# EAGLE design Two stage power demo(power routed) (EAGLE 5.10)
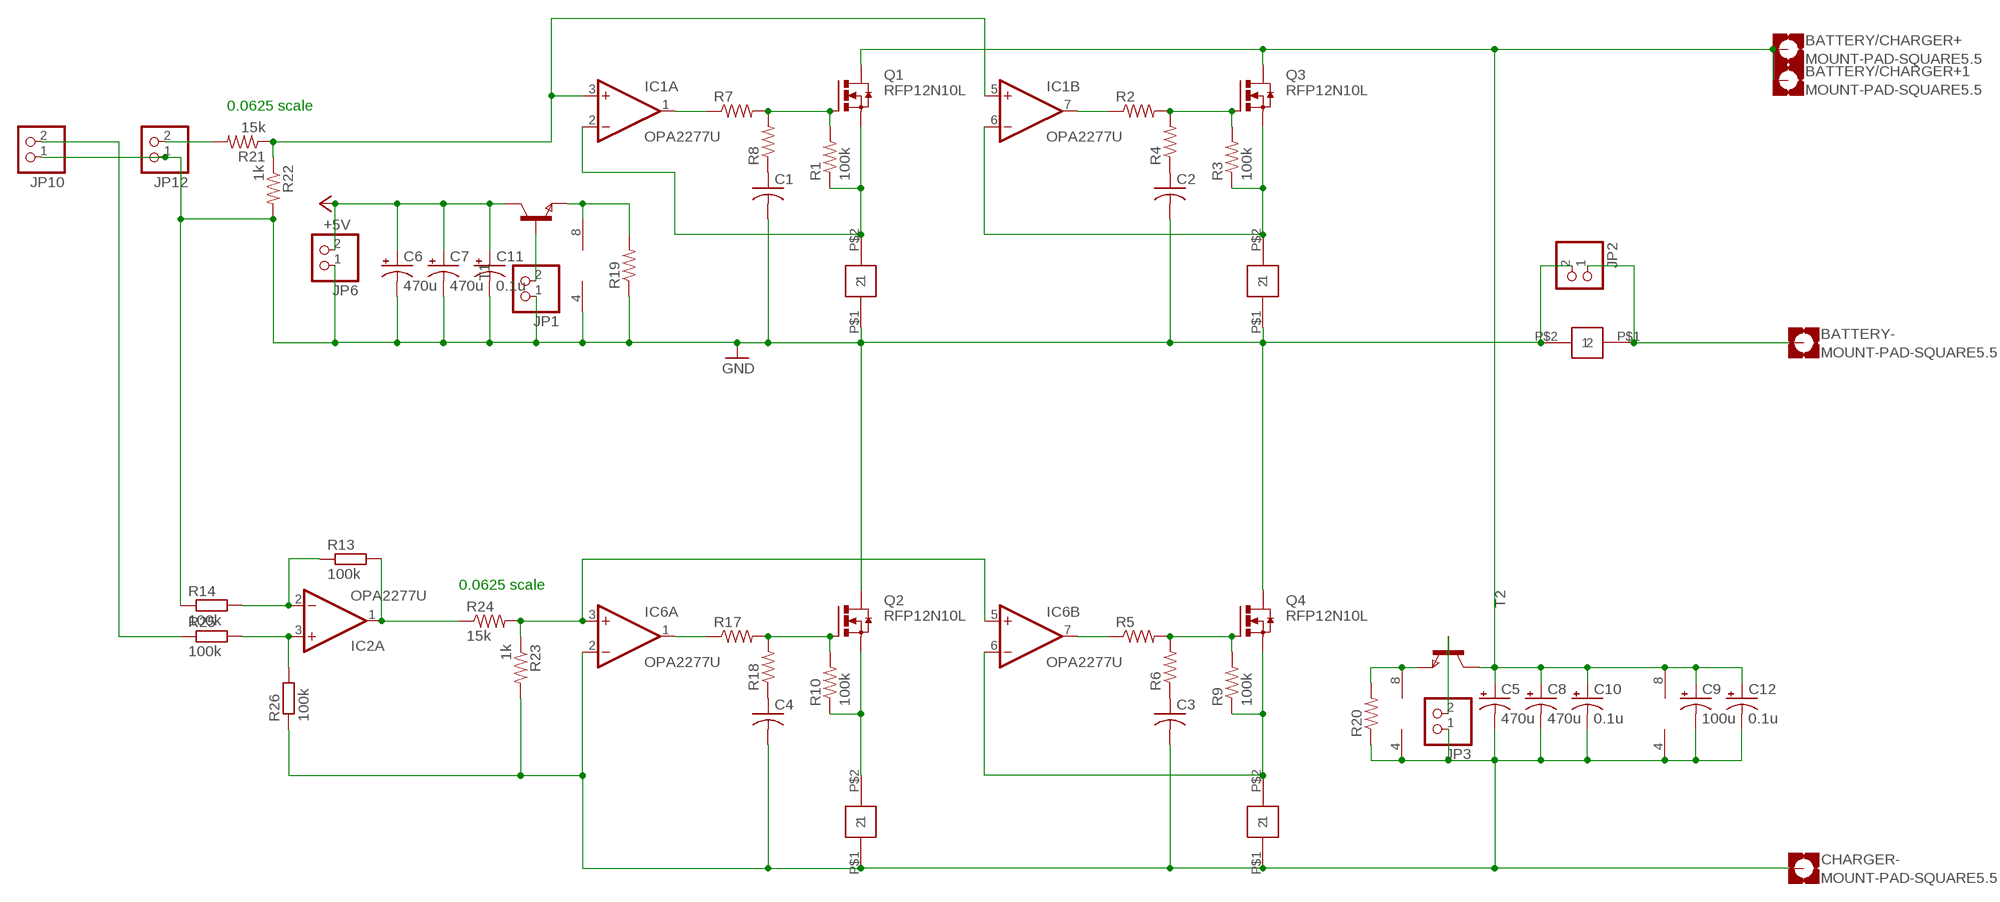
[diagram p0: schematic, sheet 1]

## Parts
1  630HR050E  [630HR050E]
BATTERY-  MOUNT-PAD-SQUARE5.5  [5,5-PAD-SQUARE]
BATTERY/CHARGER+  MOUNT-PAD-SQUARE5.5  [5,5-PAD-SQUARE]
BATTERY/CHARGER+1  MOUNT-PAD-SQUARE5.5  [5,5-PAD-SQUARE]
C1  C-US150-054X183  [C150-054X183]
C2  C-US150-054X183  [C150-054X183]
C3  C-US150-054X183  [C150-054X183]
C4  C-US150-054X183  [C150-054X183]
C5  470u  CPOL-USE5-10.5  [E5-10,5]
C6  470u  CPOL-USE5-10.5  [E5-10,5]
C7  470u  CPOL-USE5-10.5  [E5-10,5]
C8  470u  CPOL-USE5-10.5  [E5-10,5]
C9  100u  CPOL-USE2.5-7  [E2,5-7]
C10  0.1u  CPOL-USE2-4  [E2-4]
C11  0.1u  CPOL-USE2-4  [E2-4]
C12  0.1u  CPOL-USE2-4  [E2-4]
CHARGER-  MOUNT-PAD-SQUARE5.5  [5,5-PAD-SQUARE]
IC1  OPA2277U  [SO08]
IC2  OPA2277U  [SO08]
IC6  OPA2277U  [SO08]
JP1  PINHD-1X2  [1X02]
JP2  PINHD-1X2  [1X02]
JP3  PINHD-1X2  [1X02]
JP6  PINHD-1X2  [1X02]
JP10  PINHD-1X2  [1X02]
JP12  PINHD-1X2  [1X02]
Q1  RFP12N10L  [TO220-W/657-20ABP]
Q2  RFP12N10L  [TO220-W/657-20ABP]
Q3  RFP12N10L  [TO220-W/657-20ABP]
Q4  RFP12N10L  [TO220-W/657-20ABP]
R1  100k  R-US_0411/12  [0411/12]
R2  R-US_0411/12  [0411/12]
R3  100k  R-US_0411/12  [0411/12]
R4  R-US_0411/12  [0411/12]
R5  R-US_0411/12  [0411/12]
R6  R-US_0411/12  [0411/12]
R7  R-US_0411/12  [0411/12]
R8  R-US_0411/12  [0411/12]
R9  100k  R-US_0411/12  [0411/12]
R10  100k  R-US_0411/12  [0411/12]
R13  100k  R-EU_R0805  [R0805]
R14  100k  R-EU_R0805  [R0805]
R17  R-US_0411/12  [0411/12]
R18  R-US_0411/12  [0411/12]
R19  R-US_0411/12  [0411/12]
R20  R-US_0411/12  [0411/12]
R21  15k  R-US_0411/12  [0411/12]
R22  1k  R-US_0411/12  [0411/12]
R23  1k  R-US_0411/12  [0411/12]
R24  15k  R-US_0411/12  [0411/12]
R25  100k  R-EU_R0805  [R0805]
R26  100k  R-EU_R0805  [R0805]
T1  NPNSOT323  [SOT323]
T2  NPNSOT323  [SOT323]
U$2  630HR050E  [630HR050E]
U$3  630HR050E  [630HR050E]
U$4  630HR050E  [630HR050E]
U$5  630HR050E  [630HR050E]

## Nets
+5V: C6.+ C7.+ C11.+ JP6.2 T1.1(C)
GND: 1.P$1 C1.2 C2.2 C6.- C7.- C11.- IC1.4(P:V-) JP1.1 JP2.2 JP6.1 JP10.1 JP12.1 Q2.2(D) Q4.2(D) R14.1 R19.1 R22.2 U$2.P$2 U$4.P$1
LOAD: BATTERY/CHARGER+1.B5,5(MOUNT) BATTERY/CHARGER+.B5,5(MOUNT) C5.+ C8.+ C9.+ C10.+ C12.+ IC2.8(P:V+) Q1.2(D) Q3.2(D) T2.1(C)
N$1: IC1.7(B:OUT) R2.1
N$2: Q2.3(S) R10.1 U$3.P$2
N$3: C3.2 C4.2 C5.- C8.- C9.- C10.- C12.- CHARGER-.B5,5(MOUNT) IC2.4(P:V-) IC6.2(A:-IN) IC6.4(P:V-) JP3.1 R20.1 R23.2 R26.1 U$3.P$1 U$5.P$1
N$4: IC2.2(A:-IN) R13.1 R14.2
N$5: BATTERY-.B5,5(MOUNT) JP2.1 U$2.P$1
N$6: IC1.8(P:V+) R19.2 T1.3(E)
N$7: JP1.2 T1.2(B)
N$8: IC2.1(A:OUT) R13.2 R24.1
N$9: IC1.6(B:-IN) Q3.3(S) R3.1 U$4.P$2
N$10: Q1.1(G) R1.2 R7.2 R8.2
N$11: IC1.3(A:+IN) IC1.5(B:+IN) R21.1 R22.1
N$12: IC6.6(B:-IN) Q4.3(S) R9.1 U$5.P$2
N$13: C1.1 R8.1
N$14: Q3.1(G) R2.2 R3.2 R4.2
N$15: C2.1 R4.1
N$16: Q4.1(G) R5.2 R6.2 R9.2
N$18: C3.1 R6.1
N$19: IC2.3(A:+IN) R25.2 R26.2
N$20: Q2.1(G) R10.2 R17.2 R18.2
N$21: 1.P$2 IC1.2(A:-IN) Q1.3(S) R1.1
N$22: C4.1 R18.1
N$23: IC1.1(A:OUT) R7.1
N$25: IC6.7(B:OUT) R5.1
N$26: IC6.1(A:OUT) R17.1
N$27: JP12.2 R21.2
N$28: JP10.2 R25.1
N$29: IC6.8(P:V+) R20.2 T2.3(E)
N$30: IC6.3(A:+IN) IC6.5(B:+IN) R23.1 R24.2
N$32: JP3.2 T2.2(B)
Unconnected: IC2.5(B:+IN) IC2.6(B:-IN) IC2.7(B:OUT)

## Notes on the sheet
- 0.0625 scale
- 0.0625 scale

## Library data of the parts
1 U$2-U$5 = NEWPARTS:630HR050E
BATTERY- BATTERY/CHARGER+ BATTERY/CHARGER+1 CHARGER- = holes:MOUNT-PAD-SQUARE: MOUNTING PAD, square
C1-C4 = rcl:C-US: CAPACITOR, American symbol
C5-C12 = rcl:CPOL-US: POLARIZED CAPACITOR, American symbol
IC1 IC2 IC6 = linear:OPA2277: High Precision OPERATIONAL AMPLIFIERS REPLACES OP-07, OP-77, OP-177 Source: opa277.pdf
JP1-JP3 JP6 JP10 JP12 = pinhead:PINHD-1X2: PIN HEADER
Q1-Q4 = NEWPARTS:RFP12N10L: N-Channel Power MOSFET 100V; 12A; 0,2Ohm< Logic Level
R1-R10 R17-R24 = rcl:R-US_: RESISTOR, American symbol
R13 R14 R25 R26 = rcl:R-EU_: RESISTOR, European symbol
T1 T2 = zetex:NPNSOT323: NPN TRANSISTOR

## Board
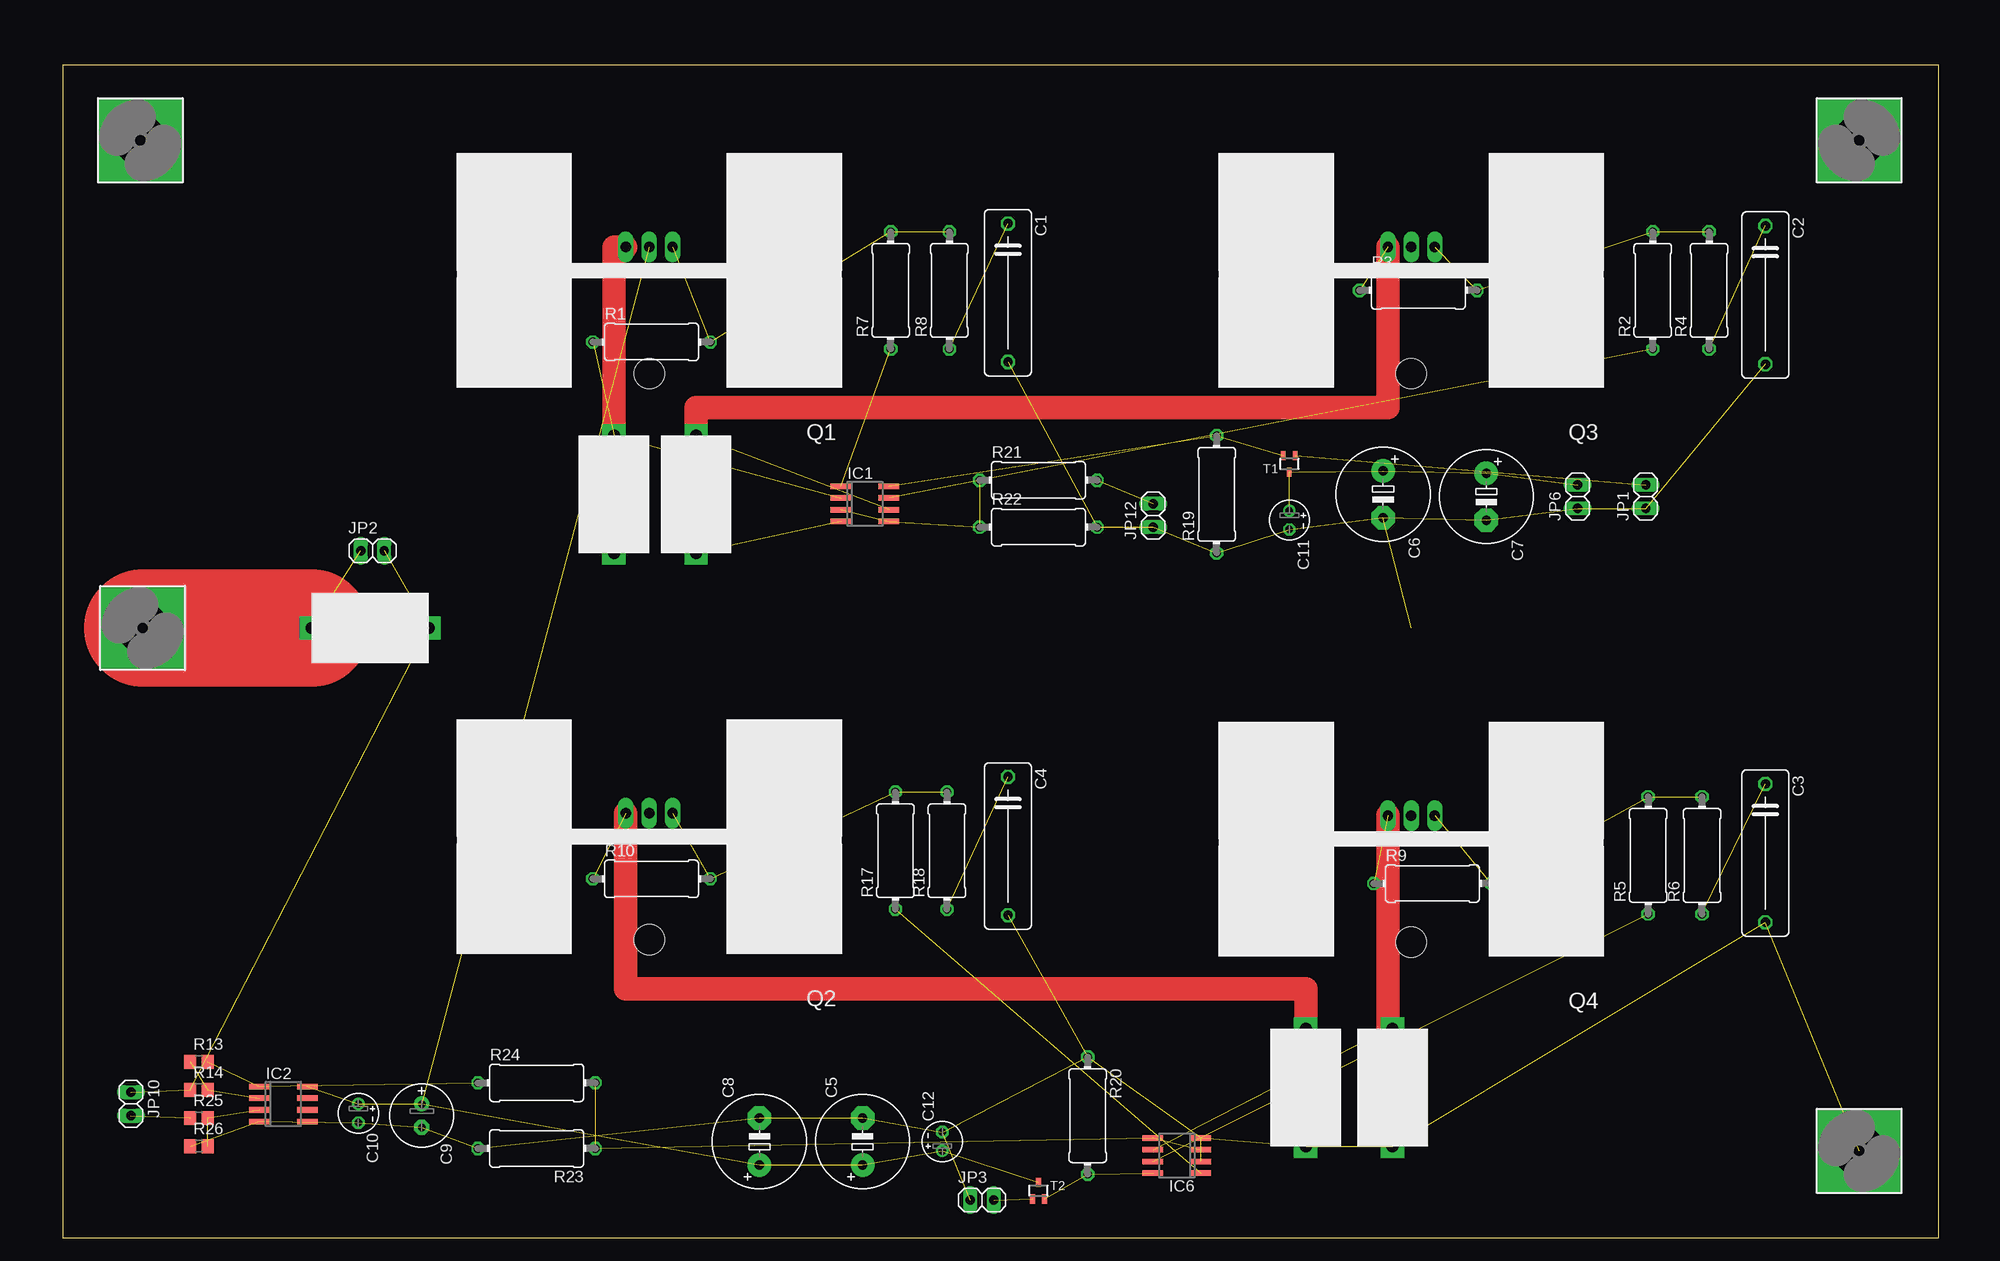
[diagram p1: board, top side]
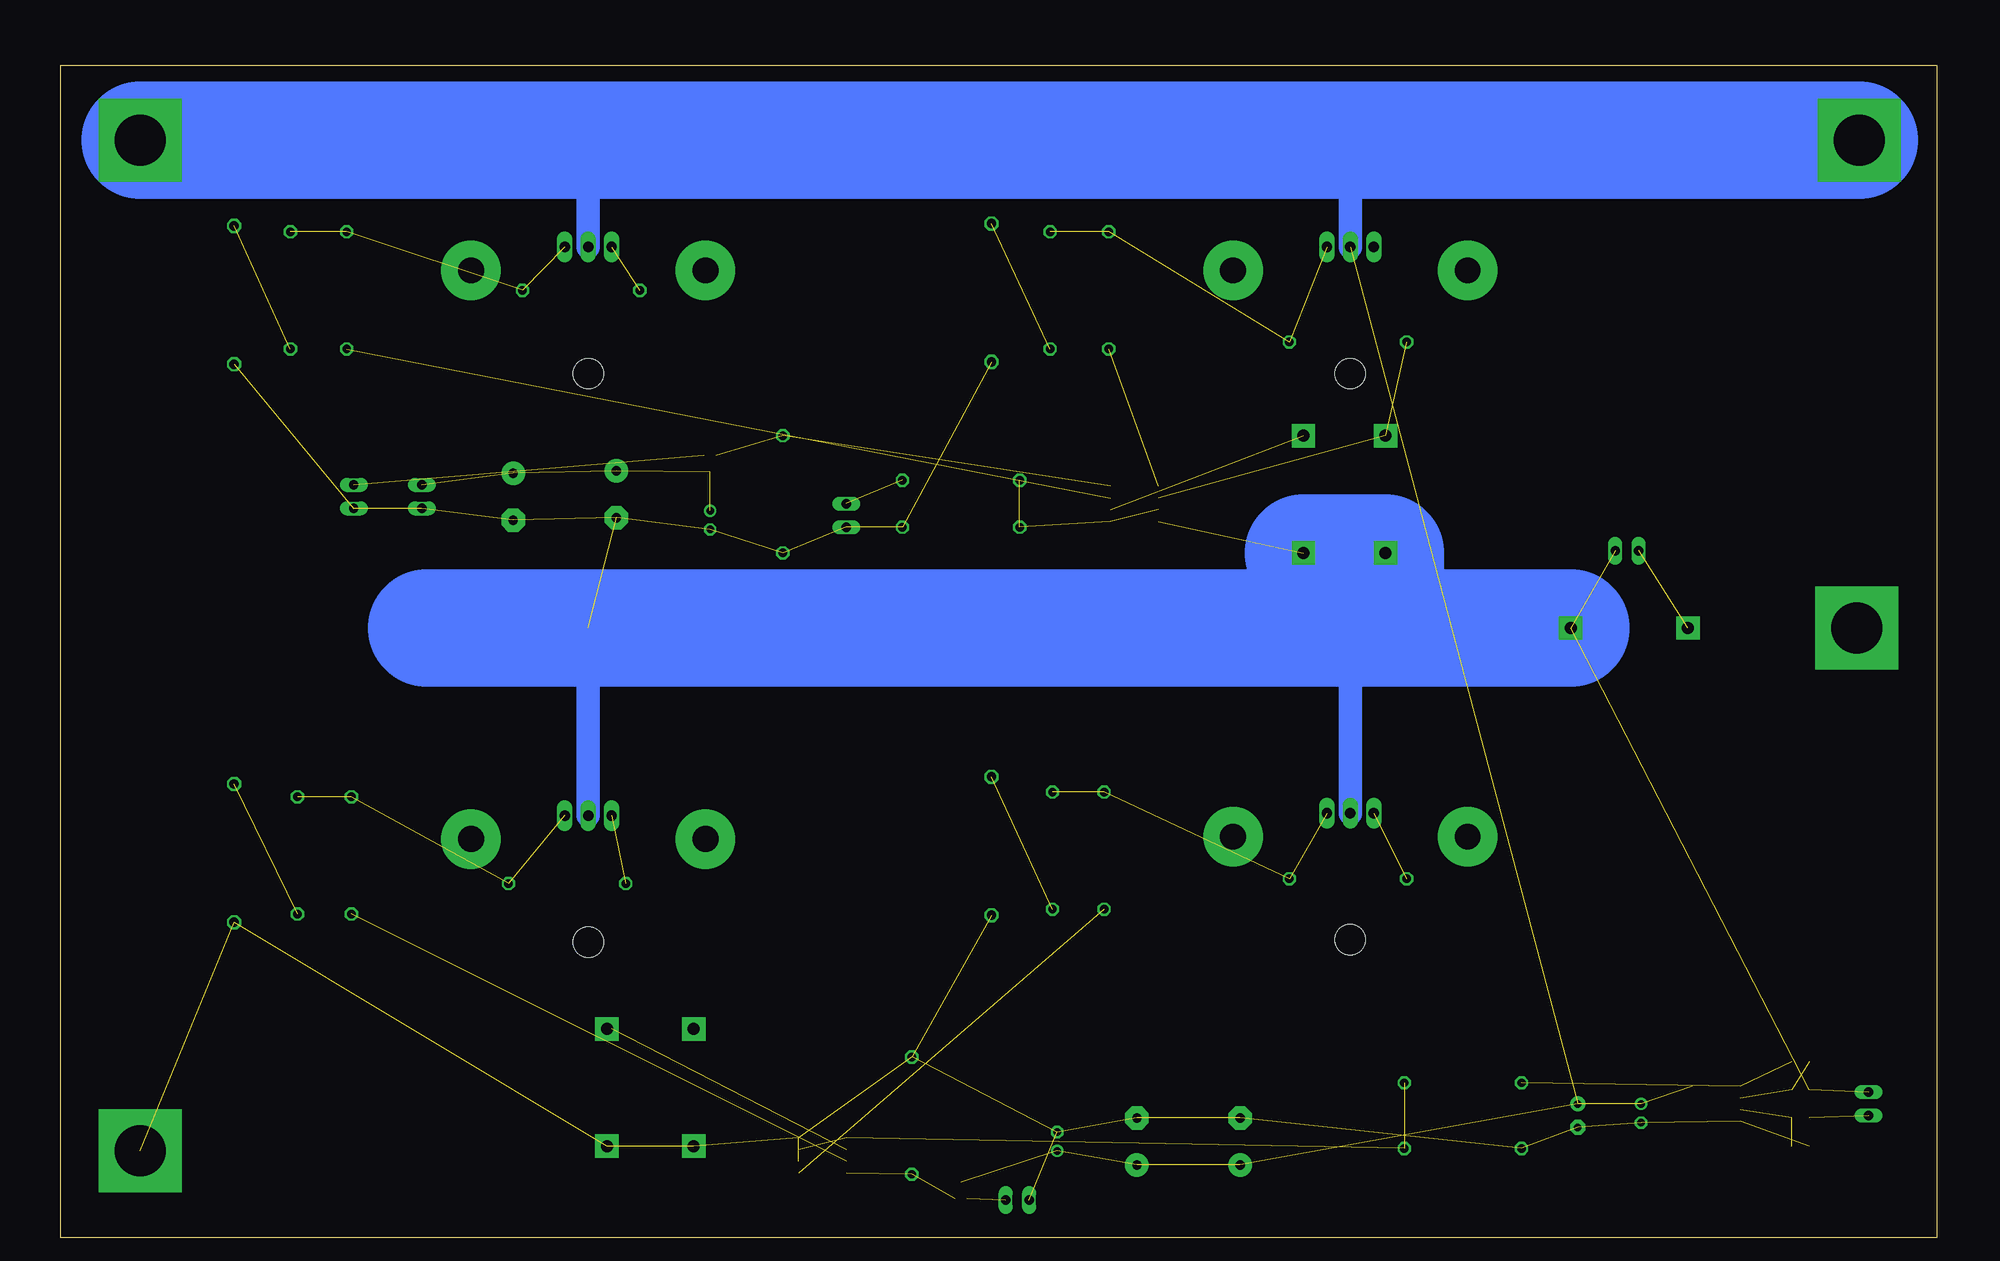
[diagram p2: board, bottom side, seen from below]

Size 203.2 x 127 mm. Coordinates in mm from the lower left corner, seen from the top.
Outline: 0,0 203.2,0 203.2,127 0,127 0,0
Copper layers (1*16): Top 0.035mm / dielectric 1.5mm / Bottom 0.035mm
Design rules "default *": minimum track width 16mil, minimum drill 24mil, track to track 8mil, track to pad 8mil, pad to pad 8mil, via to via 8mil, smd to smd 8mil, copper to edge 40mil, drill to drill 8mil, minimum pad ring 10mil, minimum via ring 8mil, stop-mask expansion 4mil, vias tented up to drill 0mil, thermal gap 10mil

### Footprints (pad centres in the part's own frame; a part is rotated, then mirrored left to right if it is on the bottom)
630HR050E = drill 1.3 pad 2.54 square: P$1 -6.35,0; P$2 6.35,0
5,5-PAD-SQUARE = drill 5.5 pad 9 square: B5,5 0,0
C150-054X183 = drill 1.016 octagon: 1 -7.493,0; 2 7.493,0
E5-10,5 = drill 1.016 pad 2.54 round: + -2.54,0 | drill 1.016 pad 2.54 octagon: - 2.54,0
E2,5-7 = drill 0.813 pad 1.6 round: + -1.27,0 | drill 0.813 pad 1.6 octagon: - 1.27,0
E2-4 = drill 0.813 pad 1.27 round: + -1.016,0 | drill 0.813 pad 1.27 octagon: - 1.016,0
SO08 = smd 0.6 x 2.2: 1 -1.905,-2.6; 2 -0.635,-2.6; 3 0.635,-2.6; 4 1.905,-2.6; 5 1.905,2.6; 6 0.635,2.6; 7 -0.635,2.6; 8 -1.905,2.6
1X02 = drill 1.016 long: 1 -1.27,0; 2 1.27,0
TO220-W/657-20ABP = drill 1.118 long: 1 -2.54,-2.54; 2 0,-2.54; 3 2.54,-2.54 | drill 2.8 pad 6.452 round: P$1 -12.7,0; P$2 12.7,0 | hole 3.302: 0,11.176
0411/12 = drill 0.914 octagon: 1 -6.35,0; 2 6.35,0
R0805 = smd 1.3 x 1.5: 1 -0.95,0; 2 0.95,0
SOT323 = smd 0.5 x 1: 1 0,0.9; 2 -0.65,-0.9; 3 0.65,-0.9

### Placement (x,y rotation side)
1  59.69,80.52 90 top
BATTERY-  8.64,66.04 90 top
BATTERY/CHARGER+  8.38,118.87 90 top
BATTERY/CHARGER+1  194.56,118.87 0 top
C1  102.36,102.36 270 top
C2  184.4,102.11 270 top
C3  184.4,41.66 270 top
C4  102.36,42.42 270 top
C5  86.61,10.41 90 top
C6  143,80.52 270 top
C7  154.18,80.26 270 top
C8  75.44,10.41 90 top
C9  38.86,13.21 270 top
C10  32,13.46 270 top
C11  132.84,77.72 270 top
C12  95.25,10.41 90 top
CHARGER-  194.56,9.4 90 top
IC1  86.87,79.5 270 top
IC2  23.88,14.48 270 top
IC6  120.65,8.89 90 top
JP1  171.45,80.26 90 top
JP2  33.53,74.42 0 top
JP3  99.57,4.06 0 top
JP6  164.08,80.26 90 top
JP10  7.37,14.48 270 top
JP12  118.11,78.23 90 top
Q1  63.5,104.78 180 top
Q2  63.5,43.43 180 top
Q3  146.05,104.78 180 top
Q4  146.05,43.18 180 top
R1  63.75,97.03 0 top
R2  172.21,102.62 90 top
R3  146.81,102.62 0 top
R4  178.31,102.62 90 top
R5  171.7,41.4 90 top
R6  177.55,41.4 90 top
R7  89.66,102.62 90 top
R8  96.01,102.62 90 top
R9  148.34,38.35 0 top
R10  63.75,38.86 0 top
R13  14.73,19.05 0 top
R14  14.73,16 0 top
R17  90.17,41.91 90 top
R18  95.76,41.91 90 top
R19  124.97,80.52 90 top
R20  111,13.21 270 top
R21  105.66,82.04 0 top
R22  105.66,76.96 0 top
R23  51.31,9.65 180 top
R24  51.31,16.76 0 top
R25  14.73,12.95 0 top
R26  14.73,9.91 0 top
T1  132.84,83.82 180 top
T2  105.66,5.08 0 top
U$2  33.27,66.04 0 top
U$3  134.62,16.26 90 top
U$4  68.58,80.52 90 top
U$5  144.02,16.26 90 top

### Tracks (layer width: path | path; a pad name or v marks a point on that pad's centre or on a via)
+5V  (4 unrouted)
GND  (14 unrouted)
  Bottom 12.7: U$2.P$2 59.69,66.04 | U$4.P$1 1.P$1 59.69,66.04 | 59.69,66.04 63.25,66.04 163.58,66.04
  Bottom 2.54: 163.58,66.04 146.05,66.04 Q4.2 | Q2.2 63.5,66.55 63.25,66.55 63.25,66.04
LOAD  (7 unrouted)
  Bottom 12.7: BATTERY/CHARGER+1.B5,5 145.8,118.87 63.5,118.87 BATTERY/CHARGER+.B5,5
  Bottom 2.54: 63.5,118.87 Q1.2 | Q3.2 146.05,123.95 145.8,123.95 145.8,118.87
N$1  (1 unrouted)
N$2  (1 unrouted)
  Top 2.54: U$3.P$2 134.62,26.92 60.96,26.92 Q2.3
N$3  (16 unrouted)
N$4  (2 unrouted)
N$5  (1 unrouted)
  Top 12.7: BATTERY-.B5,5 U$2.P$1
N$6  (2 unrouted)
N$7  (1 unrouted)
N$8  (2 unrouted)
N$9  (2 unrouted)
  Top 2.54: U$4.P$2 68.58,89.92 143.51,89.92 Q3.3
N$10  (3 unrouted)
N$11  (3 unrouted)
N$12  (2 unrouted)
  Top 2.54: Q4.3 143.51,22.61 U$5.P$2
N$13  (1 unrouted)
N$14  (3 unrouted)
N$15  (1 unrouted)
N$16  (3 unrouted)
N$18  (1 unrouted)
N$19  (2 unrouted)
N$20  (3 unrouted)
N$21  (2 unrouted)
  Top 2.54: Q1.3 59.69,107.31 1.P$2
N$22  (1 unrouted)
N$23  (1 unrouted)
N$25  (1 unrouted)
N$26  (1 unrouted)
N$27  (1 unrouted)
N$28  (1 unrouted)
N$29  (2 unrouted)
N$30  (3 unrouted)
N$32  (1 unrouted)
